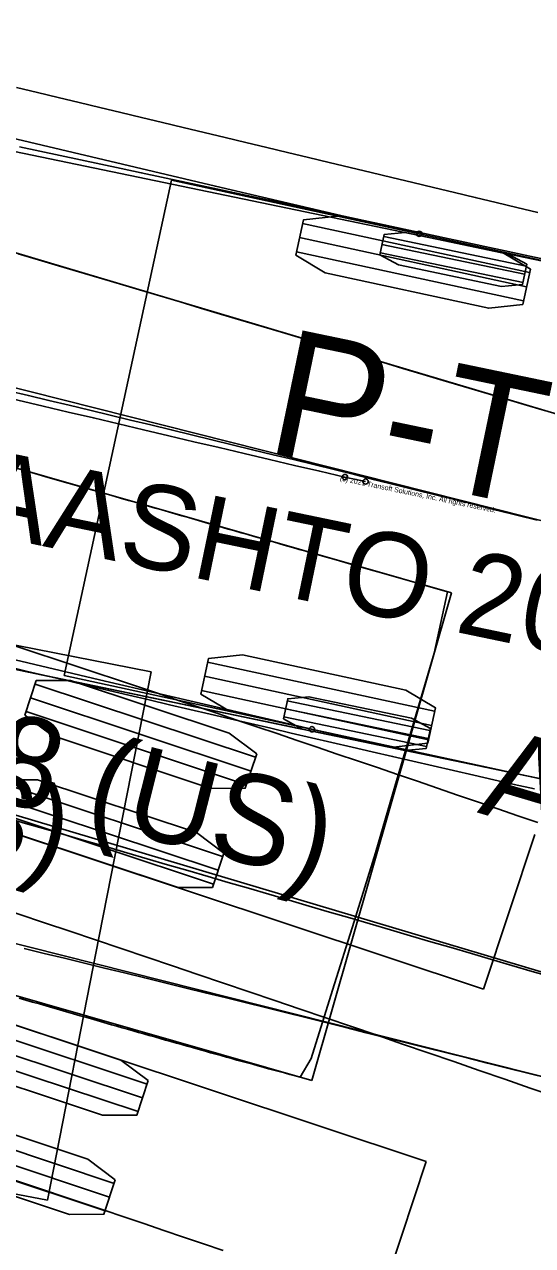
# Model space of a CAD drawing. Extents: x -14 to 1565148, y -25 to 642856.
# Drawn here: x 1565078.68 to 1565086.71, y 636499.5 to 636518.77 of the extents above; entities that cross this region are included whole.
import ezdxf

# ---------------------------------------------------------------- set-up
doc = ezdxf.new("R2010")
doc.units = 0
for name, color, linetype in [('DR_P_Headwall', 7, 'Continuous'), ('GE_P_Alignment_100_Stations', 7, 'Continuous'), ('PM_P_Edge_Line', 7, 'Continuous'), ('TR_Turning_Path27', 7, 'Continuous'), ('TR_Turning_Path29', 7, 'Continuous')]:
    doc.layers.add(name, color=color, linetype=linetype)

msp = doc.modelspace()

# ---------------------------------------------------------------- linework, layer by layer
at = {"layer": 'DR_P_Headwall'}
for p, q in [((1565085.423, 636509.797), (1565059.468, 636517.234)), ((1565083.22, 636502.107), (1565085.423, 636509.797)), ((1565057.264, 636509.544), (1565083.22, 636502.107))]:
    msp.add_line(p, q, dxfattribs=at)
for points in [[(1565078.428, 636511.802), (1565078.744, 636511.711), (1565079.06, 636511.621), (1565079.376, 636511.53), (1565079.692, 636511.439), (1565080.009, 636511.349), (1565080.114, 636511.319), (1565080.219, 636511.288), (1565080.325, 636511.258), (1565080.43, 636511.228), (1565080.535, 636511.198), (1565080.641, 636511.168), (1565080.746, 636511.137), (1565080.852, 636511.107), (1565080.957, 636511.077), (1565081.063, 636511.047), (1565081.168, 636511.016), (1565081.274, 636510.986), (1565081.38, 636510.956), (1565081.485, 636510.926), (1565081.591, 636510.895), (1565081.697, 636510.865), (1565081.902, 636510.806), (1565082.004, 636510.777), (1565082.106, 636510.748), (1565082.208, 636510.718), (1565082.31, 636510.689), (1565082.412, 636510.66), (1565082.514, 636510.631), (1565082.616, 636510.602), (1565082.718, 636510.572), (1565082.82, 636510.543), (1565082.921, 636510.514), (1565083.023, 636510.485), (1565083.125, 636510.456), (1565083.226, 636510.427), (1565083.327, 636510.398), (1565083.429, 636510.369), (1565083.53, 636510.34), (1565083.964, 636510.215), (1565084.038, 636510.194), (1565084.112, 636510.173), (1565084.186, 636510.152), (1565084.26, 636510.131), (1565084.334, 636510.109), (1565084.408, 636510.088), (1565084.482, 636510.067), (1565084.556, 636510.046), (1565084.629, 636510.025), (1565084.703, 636510.004), (1565084.776, 636509.983), (1565084.85, 636509.962), (1565084.923, 636509.941), (1565084.996, 636509.92), (1565085.069, 636509.899), (1565085.142, 636509.878), (1565085.215, 636509.857), (1565085.288, 636509.836), (1565085.361, 636509.815), (1565085.15, 636508.845), (1565084.842, 636507.796), (1565084.533, 636506.746), (1565084.225, 636505.697)], [(1565084.225, 636505.697), (1565083.887, 636504.615), (1565083.549, 636503.532), (1565083.211, 636502.45), (1565083.038, 636502.156), (1565082.955, 636502.178), (1565082.871, 636502.201), (1565082.788, 636502.223), (1565082.705, 636502.246), (1565082.622, 636502.269), (1565082.538, 636502.291), (1565082.455, 636502.314), (1565082.372, 636502.337), (1565082.289, 636502.36), (1565082.205, 636502.383), (1565082.122, 636502.405), (1565082.039, 636502.428), (1565081.956, 636502.451), (1565081.873, 636502.474), (1565081.79, 636502.497), (1565081.707, 636502.52), (1565081.623, 636502.543), (1565081.54, 636502.567), (1565081.424, 636502.599), (1565081.338, 636502.623), (1565081.253, 636502.647), (1565081.167, 636502.671), (1565081.082, 636502.695), (1565080.996, 636502.719), (1565080.911, 636502.743), (1565080.825, 636502.767), (1565080.74, 636502.791), (1565080.654, 636502.815), (1565080.569, 636502.839), (1565080.483, 636502.864), (1565080.398, 636502.888), (1565080.313, 636502.912), (1565080.227, 636502.936), (1565080.142, 636502.961), (1565080.056, 636502.985), (1565079.886, 636503.034), (1565079.778, 636503.065), (1565079.671, 636503.096), (1565079.564, 636503.126), (1565079.457, 636503.157), (1565079.349, 636503.188), (1565079.242, 636503.219), (1565079.135, 636503.25), (1565079.028, 636503.281), (1565078.921, 636503.312), (1565078.814, 636503.343), (1565078.707, 636503.374), (1565078.6, 636503.405)]]:
    msp.add_lwpolyline(points, dxfattribs=at)
at = {"layer": 'GE_P_Alignment_100_Stations'}
for p, q in [((1565117.99, 636503.414), (1565071.987, 636517.115)), ((1565081.006, 636516.311), (1565079.313, 636508.493)), ((1565095.666, 636513.135), (1565081.006, 636516.311)), ((1565083.075, 636515.629), (1565086.659, 636514.852)), ((1565083.027, 636515.405), (1565086.61, 636514.628)), ((1565082.978, 636515.181), (1565086.562, 636514.404)), ((1565069.561, 636508.968), (1565115.564, 636495.268)), ((1565081.576, 636508.706), (1565085.159, 636507.93)), ((1565079.313, 636508.493), (1565093.972, 636505.317)), ((1565079.313, 636508.493), (1565079.313, 636508.493)), ((1565081.527, 636508.482), (1565085.111, 636507.706)), ((1565081.479, 636508.258), (1565085.062, 636507.482))]:
    msp.add_line(p, q, dxfattribs=at)
for points in [[(1565084.916, 636515.464), (1565081.699, 636516.213), (1565078.473, 636516.978), (1565075.25, 636517.751), (1565072.028, 636518.534), (1565068.809, 636519.324), (1565065.591, 636520.124), (1565062.376, 636520.932), (1565059.163, 636521.749), (1565055.952, 636522.574), (1565052.744, 636523.408), (1565049.537, 636524.25), (1565046.333, 636525.101), (1565043.131, 636525.961), (1565039.932, 636526.829), (1565036.735, 636527.706), (1565034.179, 636528.414)], [(1565083.222, 636507.646), (1565079.958, 636508.405), (1565076.712, 636509.174), (1565073.467, 636509.953), (1565070.225, 636510.74), (1565066.985, 636511.535), (1565063.747, 636512.34), (1565060.511, 636513.153), (1565057.277, 636513.974), (1565054.045, 636514.805), (1565050.816, 636515.644), (1565047.589, 636516.491), (1565044.364, 636517.348), (1565041.141, 636518.213), (1565037.921, 636519.086), (1565034.703, 636519.968), (1565032.131, 636520.68)], [(1565078.56, 636517.774), (1565078.889, 636517.695), (1565079.218, 636517.616), (1565079.547, 636517.537), (1565079.876, 636517.458), (1565080.205, 636517.379), (1565080.534, 636517.3), (1565080.863, 636517.221), (1565081.192, 636517.142), (1565081.521, 636517.063), (1565081.851, 636516.984), (1565082.18, 636516.905), (1565082.509, 636516.826), (1565082.838, 636516.747), (1565083.167, 636516.668), (1565083.496, 636516.589), (1565083.826, 636516.51), (1565084.155, 636516.432), (1565084.484, 636516.353), (1565084.813, 636516.274), (1565085.142, 636516.195), (1565085.472, 636516.116), (1565085.801, 636516.038), (1565086.13, 636515.959), (1565086.459, 636515.88), (1565086.789, 636515.802)], [(1565078.584, 636515.15), (1565078.904, 636515.055), (1565079.224, 636514.959), (1565079.543, 636514.864), (1565079.863, 636514.769), (1565080.183, 636514.674), (1565080.502, 636514.579), (1565080.822, 636514.483), (1565081.141, 636514.388), (1565081.461, 636514.293), (1565081.781, 636514.198), (1565082.1, 636514.103), (1565082.42, 636514.008), (1565082.74, 636513.912), (1565083.059, 636513.817), (1565083.379, 636513.722), (1565083.698, 636513.627), (1565084.018, 636513.532), (1565084.337, 636513.436), (1565084.657, 636513.341), (1565084.977, 636513.246), (1565085.296, 636513.151), (1565085.616, 636513.056), (1565085.935, 636512.961), (1565086.255, 636512.865), (1565086.574, 636512.77), (1565086.894, 636512.675)], [(1565084.069, 636511.555), (1565083.743, 636511.626)], [(1565086.737, 636506.704), (1565086.417, 636506.777), (1565086.096, 636506.85), (1565085.776, 636506.923), (1565085.456, 636506.997), (1565085.136, 636507.07), (1565084.815, 636507.144), (1565084.495, 636507.218), (1565084.175, 636507.291), (1565083.855, 636507.365), (1565083.535, 636507.439), (1565083.214, 636507.513), (1565082.894, 636507.587), (1565082.574, 636507.662), (1565082.254, 636507.736), (1565081.934, 636507.81), (1565081.614, 636507.885), (1565081.294, 636507.959), (1565080.974, 636508.034), (1565080.654, 636508.109), (1565080.334, 636508.184), (1565080.014, 636508.259), (1565079.695, 636508.334), (1565079.375, 636508.409), (1565079.055, 636508.484), (1565078.735, 636508.559), (1565078.415, 636508.635)], [(1565087.017, 636503.733), (1565086.698, 636503.827), (1565086.378, 636503.92), (1565086.058, 636504.014), (1565085.739, 636504.108), (1565085.419, 636504.202), (1565085.099, 636504.295), (1565084.779, 636504.389), (1565084.46, 636504.483), (1565084.14, 636504.576), (1565083.82, 636504.67), (1565083.5, 636504.763), (1565083.181, 636504.857), (1565082.861, 636504.95), (1565082.541, 636505.043), (1565082.221, 636505.137), (1565081.902, 636505.23), (1565081.582, 636505.323), (1565081.262, 636505.417), (1565080.942, 636505.51), (1565080.622, 636505.603), (1565080.303, 636505.696), (1565079.983, 636505.789), (1565079.663, 636505.882), (1565079.343, 636505.975), (1565079.023, 636506.068), (1565078.703, 636506.161), (1565078.384, 636506.254)]]:
    msp.add_lwpolyline(points, dxfattribs=at)
for points in [[(1565082.966, 636515.125), (1565083.087, 636515.684), (1565083.626, 636515.744), (1565086.206, 636515.185), (1565086.671, 636514.908), (1565086.55, 636514.349), (1565086.012, 636514.289), (1565083.432, 636514.848)], [(1565081.467, 636508.202), (1565081.588, 636508.761), (1565082.126, 636508.821), (1565084.706, 636508.262), (1565085.171, 636507.985), (1565085.05, 636507.426), (1565084.512, 636507.366), (1565081.932, 636507.925)]]:
    msp.add_lwpolyline(points, close=True, dxfattribs=at)
for centre in [(1565084.916, 636515.464), (1565083.743, 636511.626), (1565083.743, 636511.626), (1565084.069, 636511.555), (1565083.222, 636507.646)]:
    msp.add_circle(centre, 0.0417, dxfattribs=at)
msp.add_arc((1565365.694, 637720.982), 1241.789, 254.467176, 256.876425, dxfattribs=at)
at = {"layer": 'PM_P_Edge_Line'}
for p, q in [((1565099.296, 636512.449), (1565072.86, 636517.941)), ((1565084.355, 636515.42), (1565086.606, 636514.952)), ((1565084.328, 636515.293), (1565086.58, 636514.825)), ((1565084.302, 636515.165), (1565086.554, 636514.697)), ((1565071.233, 636510.108), (1565097.669, 636504.616)), ((1565082.833, 636508.097), (1565085.085, 636507.629)), ((1565082.807, 636507.97), (1565085.059, 636507.502)), ((1565082.78, 636507.842), (1565085.032, 636507.374))]:
    msp.add_line(p, q, dxfattribs=at)
for points in [[(1565078.607, 636516.836), (1565078.927, 636516.768), (1565079.248, 636516.7), (1565079.568, 636516.632), (1565079.888, 636516.563), (1565080.209, 636516.495), (1565080.529, 636516.427), (1565080.849, 636516.358), (1565081.169, 636516.29), (1565081.488, 636516.222), (1565081.808, 636516.153), (1565082.128, 636516.085), (1565082.447, 636516.016), (1565082.766, 636515.948), (1565083.086, 636515.879), (1565083.405, 636515.81), (1565083.724, 636515.742), (1565084.043, 636515.673), (1565084.361, 636515.605), (1565084.68, 636515.536), (1565084.999, 636515.468), (1565085.317, 636515.399), (1565085.635, 636515.33), (1565085.954, 636515.262), (1565086.272, 636515.193), (1565086.59, 636515.125), (1565086.908, 636515.056)], [(1565086.935, 636506.844), (1565086.608, 636506.912), (1565086.281, 636506.98), (1565085.955, 636507.048), (1565085.628, 636507.117), (1565085.301, 636507.185), (1565084.975, 636507.253), (1565084.648, 636507.321), (1565084.321, 636507.389), (1565083.994, 636507.457), (1565083.667, 636507.525), (1565083.339, 636507.593), (1565083.012, 636507.661), (1565082.685, 636507.729), (1565082.357, 636507.797), (1565082.029, 636507.865), (1565081.701, 636507.933), (1565081.374, 636508.002), (1565081.046, 636508.07), (1565080.717, 636508.138), (1565080.389, 636508.206), (1565080.061, 636508.274), (1565079.732, 636508.343), (1565079.404, 636508.411), (1565079.075, 636508.479), (1565078.746, 636508.547), (1565078.418, 636508.616)]]:
    msp.add_lwpolyline(points, dxfattribs=at)
for points in [[(1565084.295, 636515.133), (1565084.361, 636515.452), (1565084.696, 636515.482), (1565086.318, 636515.145), (1565086.613, 636514.984), (1565086.547, 636514.666), (1565086.212, 636514.635), (1565084.59, 636514.972)], [(1565082.774, 636507.811), (1565082.84, 636508.129), (1565083.175, 636508.159), (1565084.796, 636507.822), (1565085.092, 636507.661), (1565085.026, 636507.343), (1565084.69, 636507.312), (1565083.069, 636507.649)]]:
    msp.add_lwpolyline(points, close=True, dxfattribs=at)
at = {"layer": 'TR_Turning_Path27'}
for p, q in [((1565080.683, 636508.555), (1565033.648, 636517.772)), ((1565032.013, 636509.43), (1565079.048, 636500.214)), ((1565079.865, 636504.384), (1565080.683, 636508.555)), ((1565082.333, 636507.205), (1565078.853, 636508.36)), ((1565082.261, 636506.987), (1565078.781, 636508.143)), ((1565082.189, 636506.77), (1565078.709, 636507.925)), ((1565085.931, 636503.548), (1565075.871, 636506.887)), ((1565081.813, 636505.639), (1565078.333, 636506.794)), ((1565081.741, 636505.421), (1565078.261, 636506.577)), ((1565081.669, 636505.204), (1565078.189, 636506.359)), ((1565086.739, 636505.984), (1565085.931, 636503.548)), ((1565079.048, 636500.214), (1565079.865, 636504.384)), ((1565074.967, 636504.166), (1565085.028, 636500.827)), ((1565080.621, 636502.048), (1565077.141, 636503.203)), ((1565080.549, 636501.831), (1565077.069, 636502.986)), ((1565080.477, 636501.613), (1565076.997, 636502.768)), ((1565080.101, 636500.482), (1565076.622, 636501.637)), ((1565080.029, 636500.265), (1565076.549, 636501.42)), ((1565079.957, 636500.047), (1565076.477, 636501.202)), ((1565085.028, 636500.827), (1565084.219, 636498.391))]:
    msp.add_line(p, q, dxfattribs=at)
for points in [[(1565078.548, 636508.959), (1565078.865, 636508.854), (1565079.183, 636508.748), (1565079.5, 636508.643), (1565079.818, 636508.537), (1565080.135, 636508.431), (1565080.452, 636508.325), (1565080.769, 636508.219), (1565081.087, 636508.112), (1565081.404, 636508.006), (1565081.721, 636507.899), (1565082.038, 636507.792), (1565082.355, 636507.685), (1565082.672, 636507.578), (1565082.988, 636507.471), (1565083.305, 636507.364), (1565083.622, 636507.256), (1565083.939, 636507.149), (1565084.256, 636507.041), (1565084.572, 636506.933), (1565084.889, 636506.825), (1565085.205, 636506.717), (1565085.522, 636506.609), (1565085.838, 636506.501), (1565086.155, 636506.392), (1565086.471, 636506.283), (1565086.788, 636506.175)], [(1565078.372, 636500.587), (1565078.686, 636500.481), (1565079, 636500.376), (1565079.314, 636500.27), (1565079.628, 636500.164), (1565079.942, 636500.058), (1565080.255, 636499.952), (1565080.569, 636499.846), (1565080.883, 636499.74), (1565081.196, 636499.634), (1565081.51, 636499.527), (1565081.823, 636499.42)]]:
    msp.add_lwpolyline(points, dxfattribs=at)
for points in [[(1565082.351, 636507.259), (1565082.171, 636506.716), (1565081.629, 636506.714), (1565079.124, 636507.546), (1565078.691, 636507.871), (1565078.871, 636508.414), (1565079.412, 636508.416), (1565081.918, 636507.584)], [(1565081.831, 636505.693), (1565081.651, 636505.15), (1565081.109, 636505.148), (1565078.604, 636505.98), (1565078.171, 636506.305), (1565078.351, 636506.848), (1565078.893, 636506.85), (1565081.398, 636506.018)], [(1565080.639, 636502.102), (1565080.459, 636501.559), (1565079.918, 636501.557), (1565077.412, 636502.389), (1565076.979, 636502.714), (1565077.159, 636503.257), (1565077.701, 636503.259), (1565080.206, 636502.427)], [(1565080.119, 636500.536), (1565079.939, 636499.993), (1565079.398, 636499.991), (1565076.892, 636500.823), (1565076.459, 636501.148), (1565076.639, 636501.691), (1565077.181, 636501.693), (1565079.686, 636500.861)]]:
    msp.add_lwpolyline(points, close=True, dxfattribs=at)
msp.add_arc((1564828.253, 635754.783), 790.626, 70.211484, 74.167159, dxfattribs=at)
at = {"layer": 'TR_Turning_Path29'}
for p, q in [((1565099.13, 636507.833), (1565052.659, 636519.564)), ((1565050.578, 636511.323), (1565097.05, 636499.591))]:
    msp.add_line(p, q, dxfattribs=at)
for points in [[(1565086.778, 636510.946), (1565086.457, 636511.026), (1565086.137, 636511.106), (1565085.816, 636511.186), (1565085.496, 636511.266), (1565085.175, 636511.346), (1565084.854, 636511.425), (1565084.534, 636511.505), (1565084.213, 636511.584), (1565083.892, 636511.664), (1565083.571, 636511.743), (1565083.25, 636511.822), (1565082.929, 636511.901), (1565082.608, 636511.979), (1565082.286, 636512.058), (1565081.965, 636512.136), (1565081.644, 636512.215), (1565081.322, 636512.293), (1565081.001, 636512.371), (1565080.679, 636512.449), (1565080.357, 636512.526), (1565080.036, 636512.604), (1565079.714, 636512.681), (1565079.392, 636512.758), (1565079.07, 636512.835), (1565078.748, 636512.911), (1565078.426, 636512.988)], [(1565086.952, 636502.139), (1565086.631, 636502.22), (1565086.311, 636502.3), (1565085.991, 636502.38), (1565085.671, 636502.461), (1565085.352, 636502.541), (1565085.033, 636502.621), (1565084.715, 636502.7), (1565084.396, 636502.78), (1565084.078, 636502.859), (1565083.76, 636502.939), (1565083.442, 636503.018), (1565083.124, 636503.097), (1565082.806, 636503.176), (1565082.488, 636503.255), (1565082.171, 636503.333), (1565081.853, 636503.412), (1565081.536, 636503.49), (1565081.218, 636503.568), (1565080.901, 636503.646), (1565080.583, 636503.724), (1565080.266, 636503.802), (1565079.949, 636503.879), (1565079.632, 636503.956), (1565079.315, 636504.033), (1565078.998, 636504.11), (1565078.681, 636504.187)]]:
    msp.add_lwpolyline(points, dxfattribs=at)

# ---------------------------------------------------------------- texts
at = {"layer": 'DR_P_Headwall'}
msp.add_text('AASHTO 2018 (US)', height=1.33333, rotation=344.0119, dxfattribs=at).set_placement((1565063.856, 636509.729))
at = {"layer": 'GE_P_Alignment_100_Stations'}
msp.add_text('AASHTO 2018 (US)', height=1.41667, rotation=343.4153, dxfattribs=at).set_placement((1565085.82, 636506.336))
at = {"layer": 'PM_P_Edge_Line'}
for s, height, p in [('P-T', 2, (1565082.453, 636512.026)), ('AASHTO 2018 (US)', 1.33333, (1565077.793, 636510.781)), ('(c) 2021 Transoft Solutions, Inc. All rights reserved.', 0.08, (1565083.66, 636511.571))]:
    msp.add_text(s, height=height, rotation=348.2636, dxfattribs=at).set_placement(p)
at = {"layer": 'TR_Turning_Path29'}
msp.add_text('AASHTO 2018 (US)', height=1.41667, rotation=345.8318, dxfattribs=at).set_placement((1565066.935, 636509.378))

doc.saveas('drawing.dxf')
